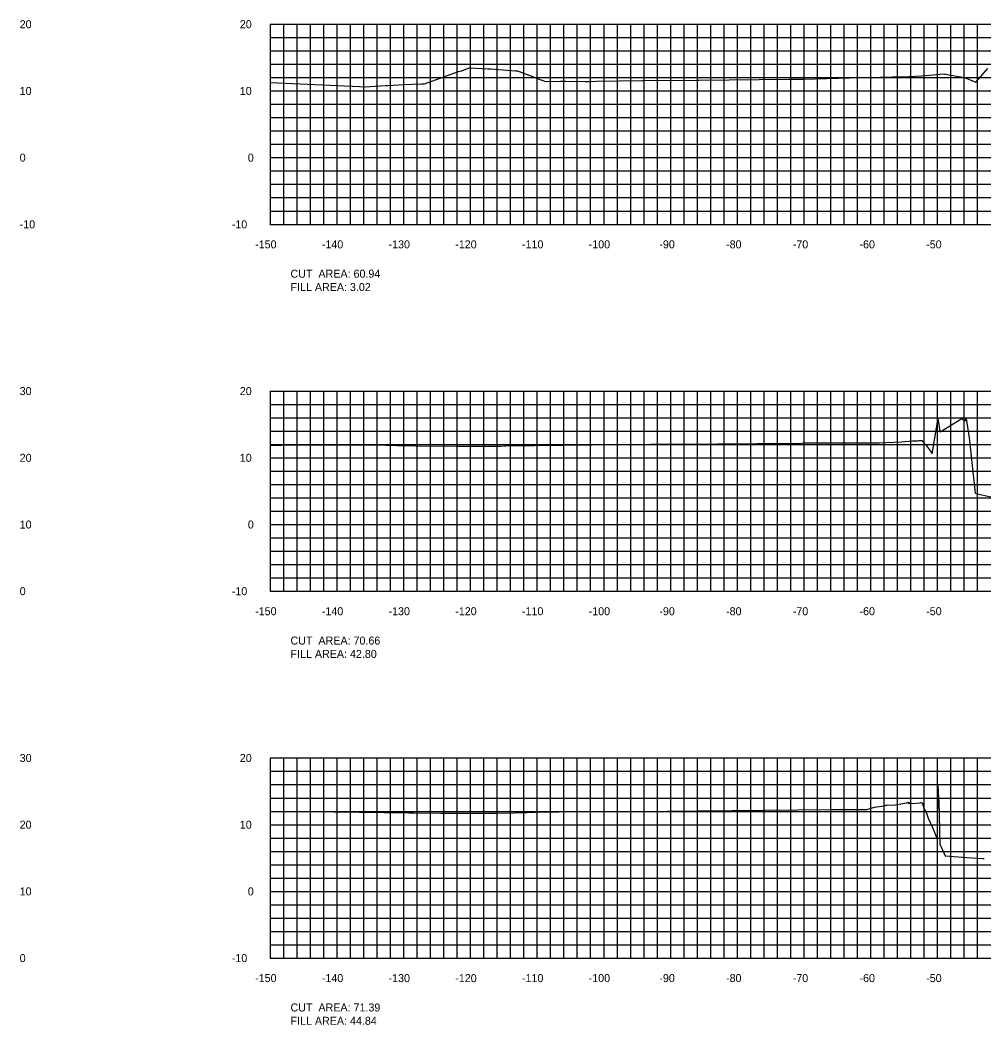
# Model space of a CAD drawing. Extents: x 1800880 to 1814006, y 250083 to 250560.
# Drawn here: x 1812643.5 to 1812788, y 250089.4 to 250240 of the extents above; entities that cross this region are included whole.
import ezdxf

# ---------------------------------------------------------------- set-up
doc = ezdxf.new("R2010")
doc.units = 0
for name, color, linetype in [('33', 7, 'Continuous'), ('CL-CNST', 7, 'Continuous'), ('DESIGN - DRAINAGE - Bridges', 7, 'Continuous'), ('DRAINAGETXT', 7, 'Continuous'), ('Level 46', 7, 'Continuous')]:
    doc.layers.add(name, color=color, linetype=linetype)

msp = doc.modelspace()

# ---------------------------------------------------------------- linework, layer by layer
at = {"layer": 'CL-CNST'}
for points in [[(1812681, 250230.71), (1812694.35, 250230.09), (1812695.18, 250230.06), (1812698.17, 250230.23), (1812698.53, 250230.24), (1812700.17, 250230.33), (1812701.01, 250230.38), (1812703.57, 250230.51), (1812703.71, 250230.51), (1812704.07, 250230.51), (1812709.18, 250232.34), (1812709.57, 250232.43), (1812709.69, 250232.46), (1812710.8, 250232.89), (1812713.6, 250232.76), (1812714.09, 250232.73), (1812714.63, 250232.67), (1812717.74, 250232.45), (1812718.04, 250232.43), (1812720.27, 250231.57), (1812720.93, 250231.34), (1812721.13, 250231.26), (1812722.25, 250230.84), (1812724.48, 250230.87), (1812724.69, 250230.88), (1812725.28, 250230.87), (1812728.18, 250230.85), (1812728.84, 250230.85), (1812729.88, 250230.88), (1812736.77, 250231.01), (1812737.09, 250231.01), (1812745.07, 250231.03), (1812745.26, 250231.03), (1812758.74, 250231.17), (1812759.49, 250231.18), (1812759.93, 250231.18), (1812760.17, 250231.19), (1812760.19, 250231.19), (1812760.76, 250231.19), (1812760.96, 250231.2), (1812769.53, 250231.43), (1812769.57, 250231.43), (1812769.72, 250231.44), (1812772.41, 250231.47), (1812773.3, 250231.49), (1812773.5, 250231.5), (1812774.22, 250231.52), (1812776.72, 250231.6), (1812778.64, 250231.67), (1812779.8, 250231.8), (1812780.34, 250231.84), (1812780.95, 250231.88), (1812781, 250231.88), (1812781.38, 250231.93), (1812782.05, 250231.99), (1812782.18, 250231.93), (1812785.02, 250231.43), (1812786.73, 250230.75), (1812788.54, 250232.78)], [(1812681, 250176.32), (1812682.47, 250176.33), (1812682.67, 250176.33), (1812693.67, 250176.39), (1812694.23, 250176.39), (1812694.39, 250176.39), (1812698.33, 250176.34), (1812698.46, 250176.33), (1812698.5, 250176.33), (1812699.23, 250176.31), (1812700, 250176.29), (1812700.85, 250176.26), (1812700.88, 250176.26), (1812701.15, 250176.26), (1812702.76, 250176.21), (1812708.83, 250176.2), (1812715.38, 250176.19), (1812715.5, 250176.19), (1812716.13, 250176.22), (1812716.21, 250176.23), (1812733.51, 250176.44), (1812733.76, 250176.44), (1812738.02, 250176.46), (1812738.35, 250176.47), (1812741.56, 250176.49), (1812741.69, 250176.49), (1812742.08, 250176.49), (1812753.92, 250176.58), (1812760.6, 250176.65), (1812760.88, 250176.66), (1812761.25, 250176.66), (1812768.24, 250176.69), (1812770.93, 250176.7), (1812772.04, 250176.7), (1812772.27, 250176.7), (1812775.58, 250176.84), (1812777.27, 250176.96), (1812777.71, 250176.98), (1812778.01, 250177), (1812778.06, 250177), (1812778.23, 250177.01), (1812778.58, 250177.03), (1812778.6, 250177.03), (1812778.63, 250177.04), (1812778.66, 250177.03), (1812778.67, 250177.03), (1812778.68, 250177.01), (1812778.71, 250176.98), (1812778.73, 250176.95), (1812778.76, 250176.92), (1812778.98, 250176.68), (1812778.99, 250176.66), (1812779.07, 250176.59), (1812779.22, 250176.43), (1812779.22, 250176.43), (1812779.95, 250175.43), (1812780.2, 250175.02), (1812781.05, 250180.06), (1812781.07, 250180.06), (1812781.07, 250180.27), (1812781.07, 250180.26), (1812781.07, 250180.26), (1812781.07, 250180.26), (1812781.07, 250180.26), (1812781.07, 250180.26), (1812781.07, 250180.26), (1812781.07, 250180.22), (1812781.07, 250180.2), (1812781.07, 250180.2), (1812781.07, 250180.2), (1812781.07, 250180.17), (1812781.08, 250180.08), (1812781.08, 250180.06), (1812781.09, 250180.06), (1812781.35, 250178.35), (1812781.4, 250178.34), (1812784.65, 250180.3), (1812785.06, 250179.94), (1812785.14, 250180), (1812785.19, 250180.03), (1812785.28, 250180.31), (1812785.72, 250177.43), (1812786.65, 250169.11), (1812787.66, 250168.88), (1812789.42, 250168.49)], [(1812681, 250121.39), (1812685.59, 250121.41), (1812685.75, 250121.41), (1812686.73, 250121.4), (1812686.8, 250121.4), (1812701.73, 250121.22), (1812702.28, 250121.19), (1812702.49, 250121.19), (1812706.56, 250121.18), (1812710.8, 250121.17), (1812714.82, 250121.15), (1812717.51, 250121.23), (1812717.98, 250121.24), (1812719.46, 250121.28), (1812719.96, 250121.29), (1812720.09, 250121.3), (1812720.3, 250121.31), (1812720.44, 250121.31), (1812720.56, 250121.32), (1812720.66, 250121.32), (1812720.68, 250121.32), (1812723.54, 250121.36), (1812724.24, 250121.36), (1812735.85, 250121.43), (1812735.99, 250121.43), (1812745.04, 250121.5), (1812745.41, 250121.5), (1812745.56, 250121.5), (1812750.22, 250121.54), (1812764.94, 250121.7), (1812765.06, 250121.7), (1812766.55, 250121.71), (1812766.82, 250121.71), (1812766.82, 250121.71), (1812766.83, 250121.71), (1812766.83, 250121.71), (1812766.85, 250121.71), (1812766.87, 250121.71), (1812766.89, 250121.71), (1812767.17, 250121.71), (1812768.44, 250121.72), (1812770.41, 250121.73), (1812771.57, 250122.05), (1812772.65, 250122.23), (1812773.11, 250122.32), (1812773.17, 250122.33), (1812773.39, 250122.38), (1812773.41, 250122.39), (1812774.37, 250122.38), (1812776.39, 250122.7), (1812776.55, 250122.83), (1812776.75, 250122.54), (1812776.92, 250122.75), (1812777.02, 250122.66), (1812777.26, 250122.61), (1812778.38, 250122.73), (1812778.41, 250122.72), (1812778.54, 250122.75), (1812778.6, 250122.7), (1812778.68, 250122.77), (1812778.78, 250122.43), (1812778.97, 250121.96), (1812779.38, 250121.03), (1812779.62, 250120.43), (1812780.26, 250118.99), (1812780.49, 250118.43), (1812780.82, 250117.68), (1812780.94, 250117.43), (1812780.94, 250117.43), (1812780.96, 250117.43), (1812780.96, 250117.43), (1812780.99, 250117.43), (1812781.02, 250117.98), (1812781.03, 250125.27), (1812781.14, 250123.52), (1812781.14, 250123.52), (1812781.15, 250123.41), (1812781.16, 250123.28), (1812781.17, 250123.2), (1812781.18, 250123.13), (1812781.19, 250122.97), (1812781.35, 250116.41), (1812781.36, 250116.4), (1812781.39, 250116.43), (1812781.51, 250116.19), (1812781.85, 250115.43), (1812781.96, 250115.2), (1812782.16, 250114.75), (1812785.37, 250114.51), (1812787.73, 250114.34), (1812787.99, 250114.36)]]:
    msp.add_lwpolyline(points, dxfattribs=at)
at = {"layer": 'DESIGN - DRAINAGE - Bridges'}
for p, q in [((1812680.94, 250239.43), (1812681, 250239.43)), ((1812681, 250209.43), (1812681, 250239.43)), ((1812680.94, 250229.43), (1812681, 250229.43)), ((1812680.94, 250219.43), (1812681, 250219.43)), ((1812680.94, 250209.43), (1812681, 250209.43)), ((1812681, 250209.43), (1812981, 250209.43)), ((1812681, 250209.37), (1812681, 250209.43)), ((1812691, 250209.37), (1812691, 250209.43)), ((1812701, 250209.37), (1812701, 250209.43)), ((1812711, 250209.37), (1812711, 250209.43)), ((1812721, 250209.37), (1812721, 250209.43)), ((1812731, 250209.37), (1812731, 250209.43)), ((1812741, 250209.37), (1812741, 250209.43)), ((1812751, 250209.37), (1812751, 250209.43)), ((1812761, 250209.37), (1812761, 250209.43)), ((1812771, 250209.37), (1812771, 250209.43)), ((1812781, 250209.37), (1812781, 250209.43)), ((1812680.94, 250184.43), (1812681, 250184.43)), ((1812681, 250154.43), (1812681, 250184.43)), ((1812680.94, 250174.43), (1812681, 250174.43)), ((1812680.94, 250164.43), (1812681, 250164.43)), ((1812680.94, 250154.43), (1812681, 250154.43)), ((1812681, 250154.43), (1812981, 250154.43)), ((1812681, 250154.37), (1812681, 250154.43)), ((1812691, 250154.37), (1812691, 250154.43)), ((1812701, 250154.37), (1812701, 250154.43)), ((1812711, 250154.37), (1812711, 250154.43)), ((1812721, 250154.37), (1812721, 250154.43)), ((1812731, 250154.37), (1812731, 250154.43)), ((1812741, 250154.37), (1812741, 250154.43)), ((1812751, 250154.37), (1812751, 250154.43)), ((1812761, 250154.37), (1812761, 250154.43)), ((1812771, 250154.37), (1812771, 250154.43)), ((1812781, 250154.37), (1812781, 250154.43)), ((1812680.94, 250129.43), (1812681, 250129.43)), ((1812681, 250099.43), (1812681, 250129.43)), ((1812680.94, 250119.43), (1812681, 250119.43)), ((1812680.94, 250109.43), (1812681, 250109.43)), ((1812680.94, 250099.43), (1812681, 250099.43)), ((1812681, 250099.43), (1812981, 250099.43)), ((1812681, 250099.37), (1812681, 250099.43)), ((1812691, 250099.37), (1812691, 250099.43)), ((1812701, 250099.37), (1812701, 250099.43)), ((1812711, 250099.37), (1812711, 250099.43)), ((1812721, 250099.37), (1812721, 250099.43)), ((1812731, 250099.37), (1812731, 250099.43)), ((1812741, 250099.37), (1812741, 250099.43)), ((1812751, 250099.37), (1812751, 250099.43)), ((1812761, 250099.37), (1812761, 250099.43)), ((1812771, 250099.37), (1812771, 250099.43)), ((1812781, 250099.37), (1812781, 250099.43))]:
    msp.add_line(p, q, dxfattribs=at)
at = {"layer": 'Level 46'}
for p, q in [((1812681, 250239.43), (1812981, 250239.43)), ((1812681, 250209.43), (1812681, 250239.43)), ((1812683, 250209.43), (1812683, 250239.43)), ((1812685, 250209.43), (1812685, 250239.43)), ((1812687, 250209.43), (1812687, 250239.43)), ((1812689, 250209.43), (1812689, 250239.43)), ((1812691, 250209.43), (1812691, 250239.43)), ((1812693, 250209.43), (1812693, 250239.43)), ((1812695, 250209.43), (1812695, 250239.43)), ((1812697, 250209.43), (1812697, 250239.43)), ((1812699, 250209.43), (1812699, 250239.43)), ((1812701, 250209.43), (1812701, 250239.43)), ((1812703, 250209.43), (1812703, 250239.43)), ((1812705, 250209.43), (1812705, 250239.43)), ((1812707, 250209.43), (1812707, 250239.43)), ((1812709, 250209.43), (1812709, 250239.43)), ((1812711, 250209.43), (1812711, 250239.43)), ((1812713, 250209.43), (1812713, 250239.43)), ((1812715, 250209.43), (1812715, 250239.43)), ((1812717, 250209.43), (1812717, 250239.43)), ((1812719, 250209.43), (1812719, 250239.43)), ((1812721, 250209.43), (1812721, 250239.43)), ((1812723, 250209.43), (1812723, 250239.43)), ((1812725, 250209.43), (1812725, 250239.43)), ((1812727, 250209.43), (1812727, 250239.43)), ((1812729, 250209.43), (1812729, 250239.43)), ((1812731, 250209.43), (1812731, 250239.43)), ((1812733, 250209.43), (1812733, 250239.43)), ((1812735, 250209.43), (1812735, 250239.43)), ((1812737, 250209.43), (1812737, 250239.43)), ((1812739, 250209.43), (1812739, 250239.43)), ((1812741, 250209.43), (1812741, 250239.43)), ((1812743, 250209.43), (1812743, 250239.43)), ((1812745, 250209.43), (1812745, 250239.43)), ((1812747, 250209.43), (1812747, 250239.43)), ((1812749, 250209.43), (1812749, 250239.43)), ((1812751, 250209.43), (1812751, 250239.43)), ((1812753, 250209.43), (1812753, 250239.43)), ((1812755, 250209.43), (1812755, 250239.43)), ((1812757, 250209.43), (1812757, 250239.43)), ((1812759, 250209.43), (1812759, 250239.43)), ((1812761, 250209.43), (1812761, 250239.43)), ((1812763, 250209.43), (1812763, 250239.43)), ((1812765, 250209.43), (1812765, 250239.43)), ((1812767, 250209.43), (1812767, 250239.43)), ((1812769, 250209.43), (1812769, 250239.43)), ((1812771, 250209.43), (1812771, 250239.43)), ((1812773, 250209.43), (1812773, 250239.43)), ((1812775, 250209.43), (1812775, 250239.43)), ((1812777, 250209.43), (1812777, 250239.43)), ((1812779, 250209.43), (1812779, 250239.43)), ((1812781, 250209.43), (1812781, 250239.43)), ((1812783, 250209.43), (1812783, 250239.43)), ((1812785, 250209.43), (1812785, 250239.43)), ((1812787, 250209.43), (1812787, 250239.43)), ((1812681, 250237.43), (1812981, 250237.43)), ((1812681, 250235.43), (1812981, 250235.43)), ((1812681, 250233.43), (1812981, 250233.43)), ((1812681, 250231.43), (1812981, 250231.43)), ((1812681, 250229.43), (1812981, 250229.43)), ((1812681, 250227.43), (1812981, 250227.43)), ((1812681, 250225.43), (1812981, 250225.43)), ((1812681, 250223.43), (1812981, 250223.43)), ((1812681, 250221.43), (1812981, 250221.43)), ((1812681, 250219.43), (1812981, 250219.43)), ((1812681, 250217.43), (1812981, 250217.43)), ((1812681, 250215.43), (1812981, 250215.43)), ((1812681, 250213.43), (1812981, 250213.43)), ((1812681, 250211.43), (1812981, 250211.43)), ((1812681, 250209.43), (1812981, 250209.43)), ((1812681, 250184.43), (1812981, 250184.43)), ((1812681, 250154.43), (1812681, 250184.43)), ((1812683, 250154.43), (1812683, 250184.43)), ((1812685, 250154.43), (1812685, 250184.43)), ((1812687, 250154.43), (1812687, 250184.43)), ((1812689, 250154.43), (1812689, 250184.43)), ((1812691, 250154.43), (1812691, 250184.43)), ((1812693, 250154.43), (1812693, 250184.43)), ((1812695, 250154.43), (1812695, 250184.43)), ((1812697, 250154.43), (1812697, 250184.43)), ((1812699, 250154.43), (1812699, 250184.43)), ((1812701, 250154.43), (1812701, 250184.43)), ((1812703, 250154.43), (1812703, 250184.43)), ((1812705, 250154.43), (1812705, 250184.43)), ((1812707, 250154.43), (1812707, 250184.43)), ((1812709, 250154.43), (1812709, 250184.43)), ((1812711, 250154.43), (1812711, 250184.43)), ((1812713, 250154.43), (1812713, 250184.43)), ((1812715, 250154.43), (1812715, 250184.43)), ((1812717, 250154.43), (1812717, 250184.43)), ((1812719, 250154.43), (1812719, 250184.43)), ((1812721, 250154.43), (1812721, 250184.43)), ((1812723, 250154.43), (1812723, 250184.43)), ((1812725, 250154.43), (1812725, 250184.43)), ((1812727, 250154.43), (1812727, 250184.43)), ((1812729, 250154.43), (1812729, 250184.43)), ((1812731, 250154.43), (1812731, 250184.43)), ((1812733, 250154.43), (1812733, 250184.43)), ((1812735, 250154.43), (1812735, 250184.43)), ((1812737, 250154.43), (1812737, 250184.43)), ((1812739, 250154.43), (1812739, 250184.43)), ((1812741, 250154.43), (1812741, 250184.43)), ((1812743, 250154.43), (1812743, 250184.43)), ((1812745, 250154.43), (1812745, 250184.43)), ((1812747, 250154.43), (1812747, 250184.43)), ((1812749, 250154.43), (1812749, 250184.43)), ((1812751, 250154.43), (1812751, 250184.43)), ((1812753, 250154.43), (1812753, 250184.43)), ((1812755, 250154.43), (1812755, 250184.43)), ((1812757, 250154.43), (1812757, 250184.43)), ((1812759, 250154.43), (1812759, 250184.43)), ((1812761, 250154.43), (1812761, 250184.43)), ((1812763, 250154.43), (1812763, 250184.43)), ((1812765, 250154.43), (1812765, 250184.43)), ((1812767, 250154.43), (1812767, 250184.43)), ((1812769, 250154.43), (1812769, 250184.43)), ((1812771, 250154.43), (1812771, 250184.43)), ((1812773, 250154.43), (1812773, 250184.43)), ((1812775, 250154.43), (1812775, 250184.43)), ((1812777, 250154.43), (1812777, 250184.43)), ((1812779, 250154.43), (1812779, 250184.43)), ((1812781, 250154.43), (1812781, 250184.43)), ((1812783, 250154.43), (1812783, 250184.43)), ((1812785, 250154.43), (1812785, 250184.43)), ((1812787, 250154.43), (1812787, 250184.43)), ((1812681, 250182.43), (1812981, 250182.43)), ((1812681, 250180.43), (1812981, 250180.43)), ((1812681, 250178.43), (1812981, 250178.43)), ((1812681, 250176.43), (1812981, 250176.43)), ((1812681, 250174.43), (1812981, 250174.43)), ((1812681, 250172.43), (1812981, 250172.43)), ((1812681, 250170.43), (1812981, 250170.43)), ((1812681, 250168.43), (1812981, 250168.43)), ((1812681, 250166.43), (1812981, 250166.43)), ((1812681, 250164.43), (1812981, 250164.43)), ((1812681, 250162.43), (1812981, 250162.43)), ((1812681, 250160.43), (1812981, 250160.43)), ((1812681, 250158.43), (1812981, 250158.43)), ((1812681, 250156.43), (1812981, 250156.43)), ((1812681, 250154.43), (1812981, 250154.43)), ((1812681, 250129.43), (1812981, 250129.43)), ((1812681, 250099.43), (1812681, 250129.43)), ((1812683, 250099.43), (1812683, 250129.43)), ((1812685, 250099.43), (1812685, 250129.43)), ((1812687, 250099.43), (1812687, 250129.43)), ((1812689, 250099.43), (1812689, 250129.43)), ((1812691, 250099.43), (1812691, 250129.43)), ((1812693, 250099.43), (1812693, 250129.43)), ((1812695, 250099.43), (1812695, 250129.43)), ((1812697, 250099.43), (1812697, 250129.43)), ((1812699, 250099.43), (1812699, 250129.43)), ((1812701, 250099.43), (1812701, 250129.43)), ((1812703, 250099.43), (1812703, 250129.43)), ((1812705, 250099.43), (1812705, 250129.43)), ((1812707, 250099.43), (1812707, 250129.43)), ((1812709, 250099.43), (1812709, 250129.43)), ((1812711, 250099.43), (1812711, 250129.43)), ((1812713, 250099.43), (1812713, 250129.43)), ((1812715, 250099.43), (1812715, 250129.43)), ((1812717, 250099.43), (1812717, 250129.43)), ((1812719, 250099.43), (1812719, 250129.43)), ((1812721, 250099.43), (1812721, 250129.43)), ((1812723, 250099.43), (1812723, 250129.43)), ((1812725, 250099.43), (1812725, 250129.43)), ((1812727, 250099.43), (1812727, 250129.43)), ((1812729, 250099.43), (1812729, 250129.43)), ((1812731, 250099.43), (1812731, 250129.43)), ((1812733, 250099.43), (1812733, 250129.43)), ((1812735, 250099.43), (1812735, 250129.43)), ((1812737, 250099.43), (1812737, 250129.43)), ((1812739, 250099.43), (1812739, 250129.43)), ((1812741, 250099.43), (1812741, 250129.43)), ((1812743, 250099.43), (1812743, 250129.43)), ((1812745, 250099.43), (1812745, 250129.43)), ((1812747, 250099.43), (1812747, 250129.43)), ((1812749, 250099.43), (1812749, 250129.43)), ((1812751, 250099.43), (1812751, 250129.43)), ((1812753, 250099.43), (1812753, 250129.43)), ((1812755, 250099.43), (1812755, 250129.43)), ((1812757, 250099.43), (1812757, 250129.43)), ((1812759, 250099.43), (1812759, 250129.43)), ((1812761, 250099.43), (1812761, 250129.43)), ((1812763, 250099.43), (1812763, 250129.43)), ((1812765, 250099.43), (1812765, 250129.43)), ((1812767, 250099.43), (1812767, 250129.43)), ((1812769, 250099.43), (1812769, 250129.43)), ((1812771, 250099.43), (1812771, 250129.43)), ((1812773, 250099.43), (1812773, 250129.43)), ((1812775, 250099.43), (1812775, 250129.43)), ((1812777, 250099.43), (1812777, 250129.43)), ((1812779, 250099.43), (1812779, 250129.43)), ((1812781, 250099.43), (1812781, 250129.43)), ((1812783, 250099.43), (1812783, 250129.43)), ((1812785, 250099.43), (1812785, 250129.43)), ((1812787, 250099.43), (1812787, 250129.43)), ((1812681, 250127.43), (1812981, 250127.43)), ((1812681, 250125.43), (1812981, 250125.43)), ((1812681, 250123.43), (1812981, 250123.43)), ((1812681, 250121.43), (1812981, 250121.43)), ((1812681, 250119.43), (1812981, 250119.43)), ((1812681, 250117.43), (1812981, 250117.43)), ((1812681, 250115.43), (1812981, 250115.43)), ((1812681, 250113.43), (1812981, 250113.43)), ((1812681, 250111.43), (1812981, 250111.43)), ((1812681, 250109.43), (1812981, 250109.43)), ((1812681, 250107.43), (1812981, 250107.43)), ((1812681, 250105.43), (1812981, 250105.43)), ((1812681, 250103.43), (1812981, 250103.43)), ((1812681, 250101.43), (1812981, 250101.43)), ((1812681, 250099.43), (1812981, 250099.43))]:
    msp.add_line(p, q, dxfattribs=at)

# ---------------------------------------------------------------- texts
for s, p in [('-150', (1812678.7, 250205.83)), ('-140', (1812688.7, 250205.83)), ('-130', (1812698.7, 250205.83)), ('-120', (1812708.7, 250205.83)), ('-110', (1812718.7, 250205.83)), ('-100', (1812728.7, 250205.83)), ('-90', (1812739.3, 250205.83)), ('-80', (1812749.3, 250205.83)), ('-70', (1812759.3, 250205.83)), ('-60', (1812769.3, 250205.83)), ('-50', (1812779.3, 250205.83)), ('-150', (1812678.7, 250150.83)), ('-140', (1812688.7, 250150.83)), ('-130', (1812698.7, 250150.83)), ('-120', (1812708.7, 250150.83)), ('-110', (1812718.7, 250150.83)), ('-100', (1812728.7, 250150.83)), ('-90', (1812739.3, 250150.83)), ('-80', (1812749.3, 250150.83)), ('-70', (1812759.3, 250150.83)), ('-60', (1812769.3, 250150.83)), ('-50', (1812779.3, 250150.83)), ('-150', (1812678.7, 250095.83)), ('-140', (1812688.7, 250095.83)), ('-130', (1812698.7, 250095.83)), ('-120', (1812708.7, 250095.83)), ('-110', (1812718.7, 250095.83)), ('-100', (1812728.7, 250095.83)), ('-90', (1812739.3, 250095.83)), ('-80', (1812749.3, 250095.83)), ('-70', (1812759.3, 250095.83)), ('-60', (1812769.3, 250095.83)), ('-50', (1812779.3, 250095.83))]:
    msp.add_text(s, height=1.2).set_placement(p)
at = {"layer": '33'}
for s, p in [('20', (1812643.4, 250238.83)), ('20', (1812676.4, 250238.83)), ('10', (1812643.4, 250228.83)), ('10', (1812676.4, 250228.83)), ('0', (1812643.4, 250218.83)), ('0', (1812677.6, 250218.83)), ('-10', (1812643.4, 250208.83)), ('-10', (1812675.2, 250208.83)), ('30', (1812643.4, 250183.83)), ('20', (1812676.4, 250183.83)), ('20', (1812643.4, 250173.83)), ('10', (1812676.4, 250173.83)), ('10', (1812643.4, 250163.83)), ('0', (1812677.6, 250163.83)), ('0', (1812643.4, 250153.83)), ('-10', (1812675.2, 250153.83)), ('30', (1812643.4, 250128.83)), ('20', (1812676.4, 250128.83)), ('20', (1812643.4, 250118.83)), ('10', (1812676.4, 250118.83)), ('10', (1812643.4, 250108.83)), ('0', (1812677.6, 250108.83)), ('0', (1812643.4, 250098.83)), ('-10', (1812675.2, 250098.83))]:
    msp.add_text(s, height=1.2, dxfattribs=at).set_placement(p)
at = {"layer": 'DESIGN - DRAINAGE - Bridges'}
for p in [(1812681, 250209.43), (1812681, 250154.43), (1812681, 250099.43)]:
    msp.add_text('-', height=0.0001, dxfattribs=at).set_placement(p)
at = {"layer": 'DRAINAGETXT'}
for s, p in [('CUT  AREA: 60.94', (1812684, 250201.43)), ('FILL AREA: 3.02', (1812684, 250199.43)), ('CUT  AREA: 70.66', (1812684, 250146.43)), ('FILL AREA: 42.80', (1812684, 250144.43)), ('CUT  AREA: 71.39', (1812684, 250091.43)), ('FILL AREA: 44.84', (1812684, 250089.43))]:
    msp.add_text(s, height=1.2, dxfattribs=at).set_placement(p)

doc.saveas('drawing.dxf')
